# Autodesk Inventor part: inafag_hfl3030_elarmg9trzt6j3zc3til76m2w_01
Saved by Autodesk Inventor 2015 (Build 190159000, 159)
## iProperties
Company: TraceParts S.A.
Created: 2012-12
Part Number: inafag_hfl3030_elarmg9trzt6j3zc3til76m2w_01
Checked By: TraceParts S.A.
Catalog Web Link: www.traceparts.com
Document SubType Name: Modeling
Designer: TraceParts
Material: Generic
Density: 1 g/cm^3
Appearance: Default
Author: TraceParts
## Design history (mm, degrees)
feature "inafag_hfl3030_elarmg9trzt6j3zc3til76m2w"
body "Solid1"
